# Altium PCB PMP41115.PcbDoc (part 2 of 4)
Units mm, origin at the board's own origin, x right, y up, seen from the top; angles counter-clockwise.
Board outline 97.92 x 43.13 mm, 4 copper layers (Top Layer, Signal Layer 1, Signal Layer 2, Bottom Layer), stack 1.016 mm thick; 168 components, 122 nets, 522 pads, 2459 vias.
Unrouted connection lines stored in the file: 1.
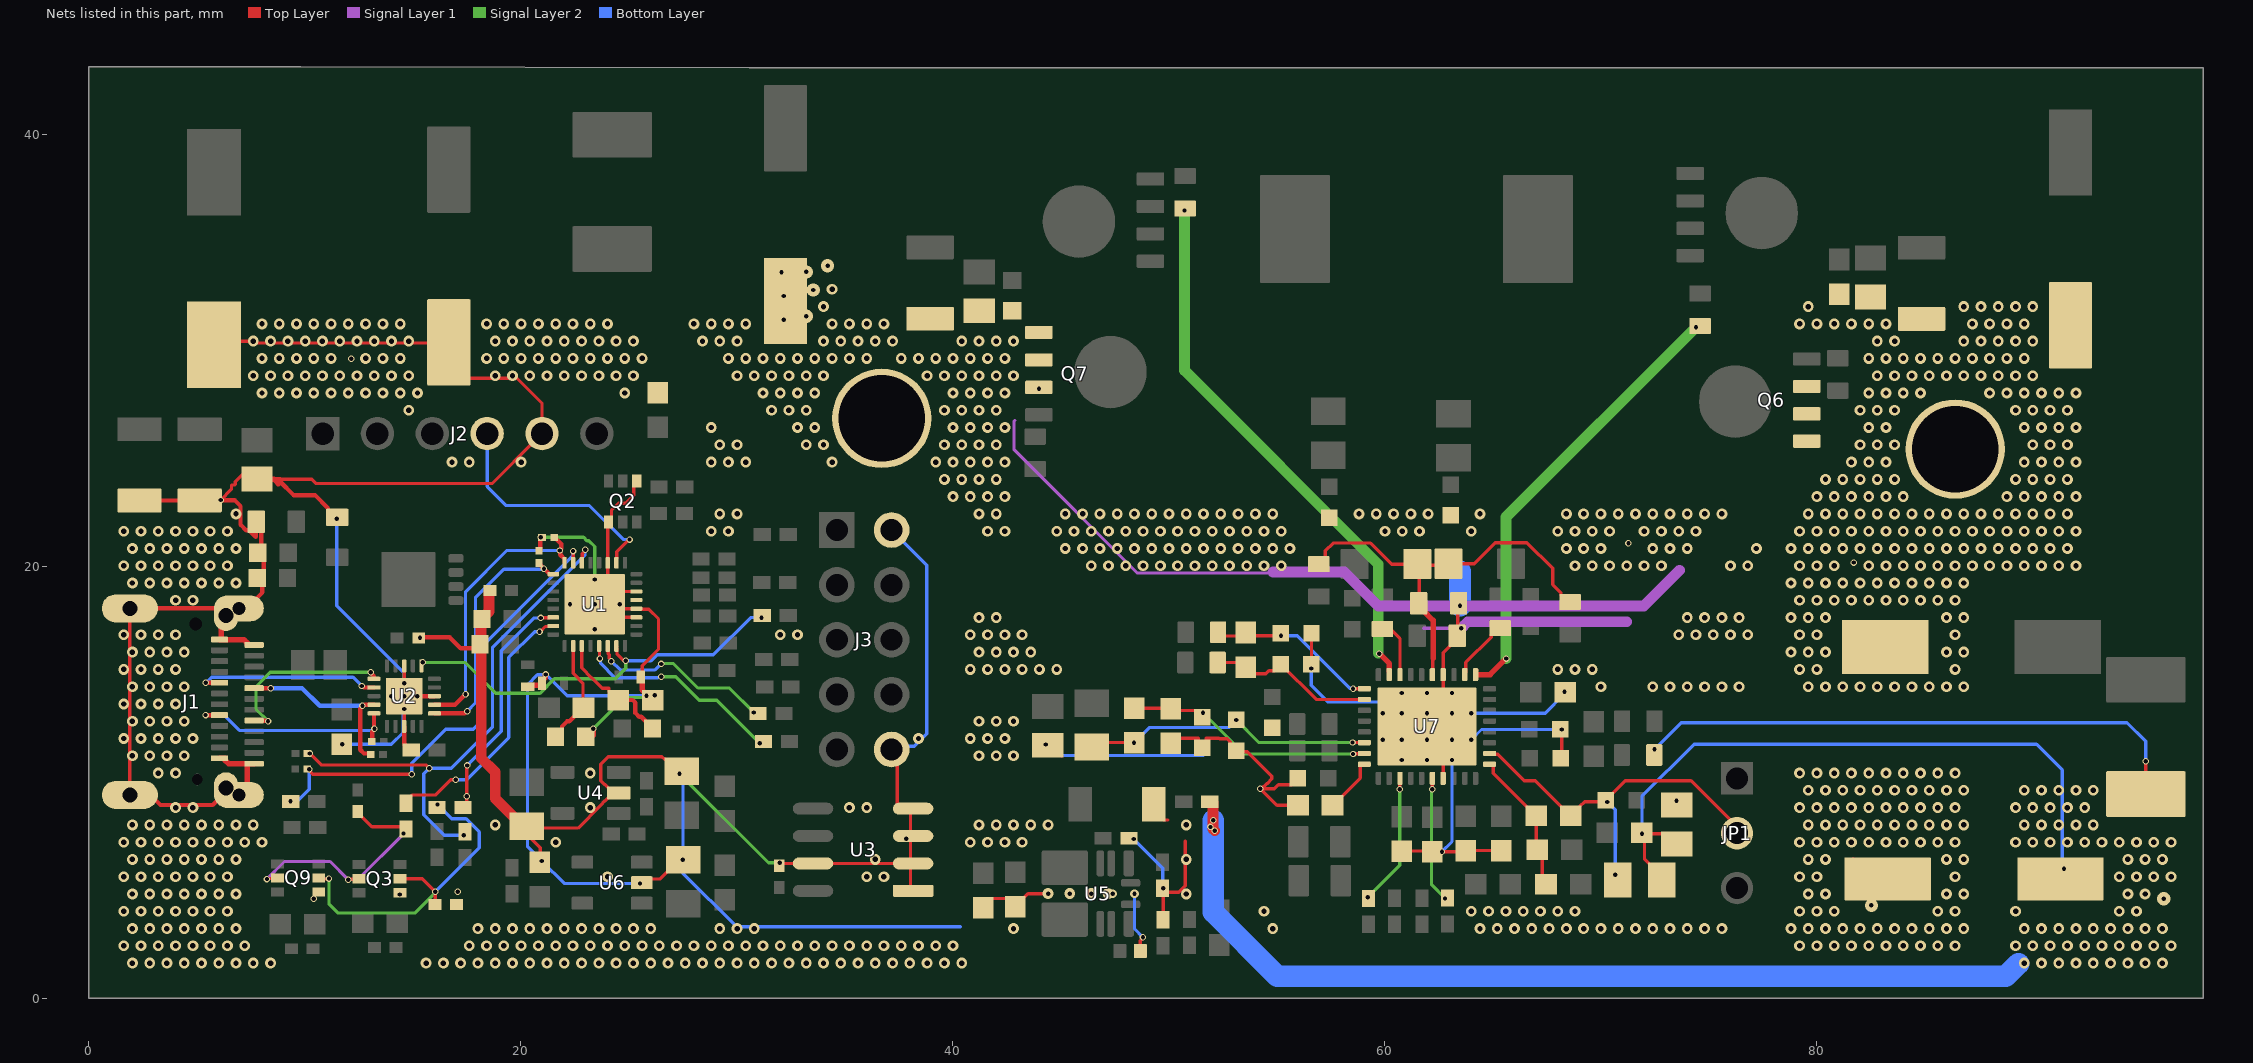
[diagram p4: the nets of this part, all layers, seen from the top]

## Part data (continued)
R31 R32 R35 R36: library part CMP-0093685-1, "RES Thick Film, 10Ω, 1%, 0.1W, 100ppm/°C, 0603", Approved Alternate Part Number=541-1.00HHCT-ND, Manufacturer=Vishay, Operating Temperature Range="-55°C to +155°C", Power=100mW, TempCo=100ppm/°C, Tolerance_%=1%, Voltage=75V
R34 R37 R43 R44 R49 R50 R53 R54 R55 R56: library part CMP-0093629-1, "Thick Film Resistors - SMD 1/10watt ZEROohm Jumper", Manufacturer=Vishay, Operating Temperature Range="-55°C to +155°C", Power=250mW, Power_W=330mW, TempCo=100ppm/°C, Tolerance_%=1%
R38: library part CMP-0023199-5, "RES, 5.23 k, 1%, 0.1 W, 0603", Manufacturer=Yageo, Power_W=100mW, Supplier Part Number 1=311-5.23KHRCT-ND, TempCo="100 ppm/C", Tolerance_%=1%, Value2=0.1W, Value_Code=5k23, ValueDisplayed=5.23k
R39: library part CMP-0022684-2, "RES, 10.0 k, 1%, 0.1 W, 0603", Manufacturer=Panasonic, Power_W=100mW, Supplier Part Number 1=P10.0KHCT-ND, TempCo="100 ppm/C", Tolerance_%=1%, Value2=0.1W, Value_Code=10k0, ValueDisplayed=10.0k
R40: library part CMP-0023018-5, "RES, 30.1 k, 1%, 0.1 W, 0603", Manufacturer=Yageo, Power_W=100mW, Supplier Part Number 1=311-30.1KHRCT-ND, TempCo="100 ppm/C", Tolerance_%=1%, Value2=0.1W, Value_Code=30k1, ValueDisplayed=30.1k
R41 R42: library part CMP-0020812-2, "RES, 2.2, 5%, 0.125 W, 0805", Manufacturer="Yageo America", Power_W=125mW, Supplier Part Number 1=311-2.2ARCT-ND, TempCo="200 ppm/C", Tolerance_%=5%, Value2=0.125W, Value_Code=2R20, ValueDisplayed=2.2
R45: library part CMP-0021522-3, "Thick Film Resistors - SMD 1/8Watt 1Mohms 1% Commercial Use", Manufacturer="Vishay / Dale", Power_W=125mW, Supplier Part Number 1=P1.00MCCT-ND, TempCo="100 ppm/C", Tolerance_%=1%, Value2=0.125W, Value_Code=1M00, ValueDisplayed=1.00M
R46: library part CMP-0024170-1, "RES, 383 k, 0.1%, 0.1 W, 0603", Manufacturer="Yageo America", Power_W=100mW, TempCo="25 ppm/C", Tolerance_%=0.1%, Value2=0.1W, Value_Code=383k
R47: library part CMP-0024106-3, "RES, 31.2 k, 0.1%, 0.1 W, 0603", Manufacturer="Yageo America", Power_W=100mW, TempCo="25 ppm/C", Tolerance_%=0.1%, Value2=0.1W, Value_Code=31k2, ValueDisplayed=31.2k
R51: library part CMP-0025744-3, "RES, 1.1, 5%, 0.1 W, 0603", Manufacturer=Vishay-Dale, Power_W=100mW, Supplier Part Number 1=541-1.1GCT-ND, TempCo="200 ppm/C", Tolerance_%=5%, Value2=0.1W, Value_Code=1R10, ValueDisplayed=1.1
R52: library part CMP-0018933-2, "Thick Film Resistors - SMD 0805 Anti-Surge Res. 0.1%, 249Kohm", Manufacturer=Panasonic, Power_W=125mW, Supplier Part Number 1=RG20P249KBCT-ND, TempCo="25 ppm/C", Tolerance_%=0.1%, Value2=0.125W, Value_Code=249k
R57: library part CMP-0023733-2, "RES, 13.7 k, 0.1%, 0.1 W, 0603", Manufacturer="Yageo America", Power_W=100mW, TempCo="25 ppm/C", Tolerance_%=0.1%, Value2=0.1W, Value_Code=13k7, ValueDisplayed=13.7k
R58: library part CMP-0024097-2, "RES, 30.5 k, 0.1%, 0.1 W, 0603", Manufacturer="Yageo America", Power_W=100mW, TempCo="25 ppm/C", Tolerance_%=0.1%, Value2=0.1W, Value_Code=30k5, ValueDisplayed=30.5k
R59: library part CMP-0023735-1, "RES, 13.0 k, 0.1%, 0.1 W, 0603", Manufacturer="Yageo America", Power_W=100mW, TempCo="25 ppm/C", Tolerance_%=0.1%, Value2=0.1W, Value_Code=13k0, ValueDisplayed=13.0k
R61: library part CMP-0022371-2, "RES, 3.01 k, 1%, 0.1 W, 0603", Manufacturer=Vishay-Dale, Power_W=100mW, Supplier Part Number 1=541-3.01KHCT-ND, TempCo="100 ppm/C", Tolerance_%=1%, Value2=0.1W, Value_Code=3k01, ValueDisplayed=3.01k
R63 R64: library part CMP-0092857-1, "Thick Film Resistors - SMD 1/8watt ZEROohm Jumper", Manufacturer=Vishay, Operating Temperature Range="-55°C to +155°C", Power_W=500mW, TempCo=200ppm/°C, Tolerance_%=5%
R65: library part CMP-0023086-5, "RES, 3.60 k, 1%, 0.1 W, 0603", Manufacturer=Yageo, Power_W=100mW, Supplier Part Number 1=311-3.60KHRCT-ND, TempCo="100 ppm/C", Tolerance_%=1%, Value2=0.1W, Value_Code=3k60, ValueDisplayed=3.60k
R67 R68 R69 R70: library part CMP-0078781-1, "RES, 10.5 k, 1%, 0.063 W, 0402", Manufacturer="Yageo America", Power_W=63mW, Supplier Part Number 1=YAG2951CT-ND, TempCo="100 ppm/C", Tolerance_%=1%, Value2=0.063W, Value_Code=10k5, ValueDisplayed=10.5k
R71: library part CMP-0023607-3, "RES, 8.20 k, 0.1%, 0.1 W, 0603", Manufacturer="Susumu Co Ltd", Power_W=100mW, Supplier Part Number 1=RG16P8.2KBCT-ND, TempCo="25 ppm/C", Tolerance_%=0.1%, Value2=0.1W, Value_Code=8k20, ValueDisplayed=8.20k
R97 R108: library part CMP-0026745-1, "RES, 100 k, 1%, 0.063 W, 0402", Manufacturer="Samsung Electro-Mechanics", Power_W=63mW, Supplier Part Number 1=1276-3432-1-ND, TempCo="100 ppm/C", Tolerance_%=1%, Value2=0.063W, Value_Code=100k
R101 R102: library part CMP-0023490-1, "RES, 249 k, 0.1%, 0.1 W, 0603", Manufacturer="Susumu Co Ltd", Power_W=100mW, Supplier Part Number 1=RG16P249KBCT-ND, TempCo="25 ppm/C", Tolerance_%=0.1%, Value2=0.1W, Value_Code=249k
R105 R106: library part CMP-0026660-1, "RES, 1.00 M, 1%, 0.1 W, 0402", Manufacturer=Panasonic, Power_W=100mW, Supplier Part Number 1=P1.00MLCT-ND, TempCo="100 ppm/C", Tolerance_%=1%, Value2=0.1W, Value_Code=1M00, ValueDisplayed=1.00M
U1: library part CMP-0121143-2, "USB Type-C® and USB PD Controller with Integrated Power Switches Optimized for Power Applications", Manufacturer="Texas Instruments", Max Supply Voltage=22V, Min Supply Voltage=3V, Nominal Supply Current=1-3mA, Operating Temperature Range="-40°C to +125°C"
U2: library part CMP-0034161-1, "USB Type-C® 48V EPR Port Protector: Short-to-VBUS Overvoltage and IEC ESD Protection", Manufacturer="Texas Instruments", Operating Supply Voltage=3.3V, Operating Temperature Range="-40°C to +125°C"
U3: library part CMP-0091847-1, "EEPROM Memory IC 512Kb (64K x 8) I²C 1MHz 900ns 8-SOIC", Digikey Part Number=CAT24C512WI-GT3OSCT-ND, Frequency_Fixed=1MHz, Manufacturer="ON Semi", Max Supply Voltage=5.5V, Min Supply Voltage=1.8V, Mouser Part Number=863-CAT24C512WI-GT3, Operating Temperature Range="-40°C to +85°C"
U4: library part CMP-0096923-1, "Linear Voltage Regulator IC  1 Output  200mA SOT-23-5", Digikey Part Number=296-TPS7A2450DBVRCT-ND, Dropout Voltage=160mV, Manufacturer="Texas Instruments", Max Supply Voltage=18V, Min Supply Voltage=2.4V, Mouser Part Number=595-TPS7A2450DBVR, Nominal Supply Current=2-15uA, Operating Temperature Range="-40°C to +125°C", Output Voltage=5V
U5: library part CMP-0096774-1, "3 V to 65 V Input, 1 V to 13 V Output, 600-mA Synchronous Buck Converter Power Module in a HotRod™ QFN Package", Manufacturer="Texas Instruments", Max Supply Voltage=65V, Min Supply Voltage=3.6V, Nominal Supply Current=17-18uA, Operating Temperature Range="-40°C to +125°C", Output Voltage=1-13V, Switching Frequency=200-2200kHz
U6: library part CMP-0035539-1, "Single Output LDO, 150 mA, Fixed 3.3 V Output, 2.7 to 10 V Input, with Low IQ, 5-pin SOT-23 (DBV), -40 to 125 degC, Green (RoHS & no Sb/Br)", Manufacturer="Texas Instruments"
U7: library part CMP-0093460-1, Alternate Manufacturer=None, Manufacturer="Texas Instruments", Operating Temperature Range=to

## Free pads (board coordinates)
  round 4.6 hole 4: 2(36.723,26.845) 2(86.431,25.423)

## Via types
v1: diameter 0.5, hole 0.25, Top Layer to Bottom Layer, 2147 vias
v2: diameter 0.3, hole 0.2, Top Layer to Bottom Layer, tented both sides, 193 vias
v3: diameter 0.5, hole 0.25, Top Layer to Bottom Layer, tented both sides, 61 vias
v4: diameter 0.5, hole 0.2, Top Layer to Bottom Layer, 22 vias
v5: diameter 0.5, hole 0.2, Top Layer to Bottom Layer, tented both sides, 19 vias
v6: diameter 0.61, hole 0.203, Top Layer to Bottom Layer, tented both sides, 13 vias
v7: diameter 0.35, hole 0.2, Top Layer to Bottom Layer, tented both sides, 2 vias
v8: diameter 0.4, hole 0.2, Top Layer to Bottom Layer, tented both sides, 2 vias

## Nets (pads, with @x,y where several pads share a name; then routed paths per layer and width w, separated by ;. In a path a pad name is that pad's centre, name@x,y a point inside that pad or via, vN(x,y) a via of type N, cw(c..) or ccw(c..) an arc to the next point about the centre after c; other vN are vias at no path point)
/INT: R68.1 U7.3 | length 6.1
  Top Layer w0.152: v2@60.706,9.703 60.712,9.709 60.712,10.172 U7.3@60.718,10.178
  Signal Layer 2 w0.152: v2(59.222,4.665) 60.706,6.149 v2(60.706,9.677)
/PG: R67.1 U7.6 | length 5.7
  Top Layer w0.152: U7.6@62.218,10.178 62.216,10.176 62.216,9.691 v2@62.23,9.677
  Signal Layer 2 w0.152: v2@62.179,9.576 62.179,5.239 v2(62.804,4.615)
  other v2: 62.214,9.677
ACN: C29.2 C33.1 R32.1 U7.29 | length 8.4
  Top Layer w0.152: R32.1@52.298,16.944 52.478,16.764 53.416,16.764 C29.2@53.581,16.929 ; v2(55.209,16.781) 55.2,16.781 C29.2@53.729,16.781 ; v2(58.547,14.326) v2(58.547,14.326) 59.067,14.327 U7.29@59.068,14.328 ; C29.2@53.581,16.929 C29.2@53.729,16.781 ; C29.2@53.581,16.929 C29.2@53.729,16.781 ; C29.2@53.581,16.929 C29.2@53.729,16.781
  Bottom Layer w0.152: v2(55.209,16.781) 55.964,16.781 58.392,14.354 58.519,14.354 v2(58.547,14.326)
ACOV: C39.1 R46.1 R47.2 U7.35 | length 11.7
  Top Layer w0.152: R46.1@48.421,13.42 50.112,13.42 R47.2@50.112,13.395 ; R47.2@50.165,13.437 50.281,13.32 51.435,13.32 51.571,13.184 C39.1@51.571,13.016 ; v2(58.547,11.303) 58.559,11.315 58.89,11.315 U7.35@58.903,11.303
  Top Layer w0.254: C39.1@51.571,13.016 51.571,13.193 v2(51.598,13.221)
  Signal Layer 2 w0.152: v2(51.598,13.221) 53.516,11.303 v2(58.547,11.303)
ACP: C29.1 C32.1 R31.1 U7.30 | length 7.9
  Top Layer w0.152: R31.1@52.277,15.539 53.472,15.539 53.632,15.38 53.632,15.253 53.861,15.024 54.512,15.024 54.65,15.162 54.893,15.162 C32.1@55.198,15.467 56.837,13.828 U7.30@59.068,13.828
ACUV: C38.1 R45.1 R46.2 U7.34 | length 13.3
  Top Layer w0.152: R45.1@46.452,11.629 46.659,11.836 R46.2@48.336,11.836 ; v2(58.522,11.836) 58.526,11.832 58.848,11.832 U7.34@58.877,11.862
  Signal Layer 2 w0.152: v2(53.138,12.88) 54.181,11.836 v2(58.522,11.836)
  Bottom Layer w0.152: v2(48.402,11.828) 49.103,12.529 52.788,12.529 v2(53.138,12.88)
ADCIN1: R13.1 R15.2 U1.2 | length 5
  Top Layer w0.152: U1.2@22.435,16.307 22.435,15.041 22.478,14.998 22.478,14.987 22.888,14.577 R13.1@22.888,13.448
  Top Layer w0.2: R15.2@21.616,12.099 21.916,12.399 21.916,12.578 22.151,12.813 22.253,12.813 22.888,13.448 R13.1@22.913,13.448
ADCIN2: R14.1 R16.2 U1.3 | length 5.8
  Top Layer w0.152: U1.3@22.835,16.307 22.835,15.29 23.304,14.821 23.312,14.821 23.782,14.352 24.089,14.352 24.089,14.276 ; R16.2@24.089,14.275 24.089,14.199 24.488,13.801 R16.2@24.513,13.801
  Top Layer w0.2: R16.2@24.513,13.801 25.196,13.801 25.313,13.683 25.313,13.201 25.489,13.026 25.588,13.026 26.105,12.508 R14.1@26.105,12.483
BAT: C60.2 C64.1 R23.2 R33.2 R36.1 R51.2 R52.2 | length 103.7
  Top Layer w0.152: R23.2@51.907,9.092 51.943,9.056 v2(51.943,7.925) ; R52.2@72.832,5.469 72.832,5.634 72.045,6.421 72.045,7.489 v2(71.922,7.612) 73.058,7.612 C64.1@73.532,7.138 ; v2(95.25,10.973) 95.25,10.236 R33.2@95.326,10.16
  Top Layer w0.254: C60.2@91.302,5.519 91.465,5.682 v6(91.465,5.994)
  Top Layer w0.5: R23.2@51.907,9.092 52.007,9.092 52.057,9.042 52.057,7.836 v2(52.146,7.747)
  Bottom Layer w0.152: v2(71.922,7.612) 71.922,9.337 74.346,11.76 90.195,11.76 91.389,10.566 91.389,5.918 v6@91.567,5.74 ; v2@72.517,11.523 72.517,11.534 73.737,12.754 94.383,12.754 95.25,11.887 v2(95.25,10.973)
  Bottom Layer w0.5: v2(51.943,7.925) v2@52.07,7.798 ; v2@52.133,7.734 52.133,7.747 v2(52.146,7.747)
  Bottom Layer w1: v2(52.07,8.23) 52.07,7.798 52.07,3.988 55.042,1.016 88.773,1.016 89.357,1.6
  other v1: 89.623,1.621 90.423,1.621 91.223,1.621 92.023,1.621 92.823,1.621 93.623,1.621 94.423,1.621 95.223,1.621 96.023,1.621 89.223,2.421 90.023,2.421 90.823,2.421 91.623,2.421 92.423,2.421 93.223,2.421 94.023,2.421 94.823,2.421 95.623,2.421 96.423,2.421 89.623,3.221 90.423,3.221 91.223,3.221 92.023,3.221 92.823,3.221 93.623,3.221 94.423,3.221 95.223,3.221 96.023,3.221 89.223,4.021 94.023,4.021 94.823,4.021 94.423,4.821 95.223,4.821 94.023,5.621 94.823,5.621 95.623,5.621 96.423,5.621 94.423,6.421 95.223,6.421 96.023,6.421 89.223,7.221 90.023,7.221 90.823,7.221 91.623,7.221 92.423,7.221 93.223,7.221 94.023,7.221 94.823,7.221 95.623,7.221 96.423,7.221 89.623,8.021 90.423,8.021 91.223,8.021 92.023,8.021 92.823,8.021 89.223,8.821 90.023,8.821 90.823,8.821 91.623,8.821 92.423,8.821 89.623,9.621 90.423,9.621 91.223,9.621 92.023,9.621 92.823,9.621
  other v2: 72.507,11.523
  other v6: 96.088,4.597
BTST1: R49.1 U7.26 | length 2.7
  Top Layer w0.152: R49.1@59.903,17.09 59.976,17.018 60.355,17.018 60.718,16.654 U7.26@60.718,14.978
BTST2: R50.1 U7.20 | length 2.8
  Top Layer w0.152: U7.20@63.754,15.062 63.767,15.075 63.767,15.545 64.938,16.716 64.938,16.836 65.237,17.135 R50.1@65.362,17.135
C_CC1: J1.A5 R10.2 U2.4 | length 8.6
  Top Layer w0.2: J1.A5@7.658,14.353 8.481,14.353 v2@8.484,14.351 ; v2(12.675,13.534) 12.675,13.507 12.572,13.404 12.572,11.501 12.748,11.325 13.009,11.325 R10.2@13.064,11.271 ; v2@12.715,13.524 12.775,13.584 U2.4@13.21,13.584
  Bottom Layer w0.2: v2@8.452,14.332 v2(8.433,14.351) 9.881,14.351 10.698,13.534 12.628,13.534 v2@12.649,13.513
C_CC2: J1.B5 R11.2 U2.5 | length 10.1
  Top Layer w0.2: v2(5.41,13.106) 5.412,13.105 6.056,13.105 J1.B5@6.058,13.103 ; R11.2@13.103,11.887 13.136,11.92 13.136,12.347 13.214,12.425 13.214,12.467 13.21,12.471 U2.5@13.21,13.184
  Bottom Layer w0.152: v2(5.41,13.106) 6.268,13.106 6.98,12.395 13.117,12.395 13.193,12.471 v2(13.233,12.471)
C_SBU1: J1.A8 U2.1 | length 8.4
  Top Layer w0.2: J1.A8@7.658,12.853 7.671,12.84 8.293,12.84 v2(8.306,12.827) ; v2(13.056,15.088) 13.056,15.061 13.208,14.908 U2.1@13.208,14.808
  Signal Layer 2 w0.152: v2(8.306,12.827) 7.747,13.386 7.747,14.427 8.407,15.088 13.005,15.088 v2@13.056,15.138
C_SBU2: J1.B8 U2.2 | length 8.7
  Top Layer w0.2: v2@5.385,14.63 5.412,14.603 v2(5.418,14.603) J1.B8@6.058,14.603 ; v2(12.649,14.453) 12.676,14.453 12.745,14.384 U2.2@13.21,14.384
  Bottom Layer w0.152: v2(5.418,14.603) 5.442,14.603 5.698,14.859 12.243,14.859 12.601,14.501 12.601,14.481 v2@12.598,14.478
CC1: C9.1 U1.24 U2.12 | length 13
  Top Layer w0.2: U2.12@16.01,13.584 16.96,13.584 17.448,14.072 v2(17.45,14.072) ; C9.1@21.553,21.337 21.573,21.337 21.886,21.025 21.886,20.821 21.819,20.753 v2(21.819,20.726) 21.838,20.707 21.838,20.529 22.035,20.332 U1.24@22.035,20.157
  Bottom Layer w0.152: v2(17.45,14.072) 17.45,18.821 19.355,20.726 v2(21.819,20.726)
CC2: C8.1 U1.25 U2.11 | length 11.5
  Top Layer w0.2: U2.11@16.01,13.184 17.398,13.184 17.499,13.284 v2(17.526,13.284) ; C8.1@20.879,20.117 20.914,20.082 20.914,20.053 21.335,19.632 U1.25@21.51,19.632
  Bottom Layer w0.152: v2(17.526,13.284) 17.907,13.665 17.907,18.542 19.228,19.863 21.014,19.863 21.031,19.88 v2@21.031,19.888
  other v2: 21.082,19.888
DRV_SUP: C43.1 D3.2 D4.2 R53.2 R55.2 U7.23 | length 20.2
  Top Layer w0.152: R53.2@56.961,20.096 56.964,20.096 57.263,20.395 57.263,20.712 57.623,21.072 59.356,21.072 60.333,20.096 D3.2@61.522,20.096 61.522,19.656 D3.2@61.633,19.546 ; C43.1@61.583,18.288 61.608,18.313 61.608,19.52 D3.2@61.633,19.546 ; D3.2@61.595,20.041 62.889,20.041 D4.2@62.962,20.114 64.152,20.114 65.128,21.09 66.596,21.09 67.788,19.898 67.788,19.148 68.171,18.764 68.171,18.639 68.47,18.341 R55.2@68.595,18.341 ; D3.2@61.633,19.985 D3.2@61.633,19.546 ; U7.23@62.218,14.978 62.237,14.996 62.237,15.704 62.255,15.723
  Top Layer w0.254: C43.1@61.773,17.973 62.255,17.49 62.255,15.735
"E_Fuse Source": J2.4 U1.18 | length 11.2
  Top Layer w0.152: U1.18@24.438,20.345 24.448,20.355 24.448,20.678 25.004,21.234 v2(25.044,21.234)
  Bottom Layer w0.152: J2.4@18.451,26.141 18.451,23.688 19.329,22.809 23.19,22.809 24.765,21.234 v2(25.044,21.234)
EPR_EN: R48.1 U1.7 U2.16 | length 18.7
  Top Layer w0.152: U1.7@24.435,16.205 U1.7@24.459,16.181 ; U1.7@24.435,16.307 U1.7@24.459,16.283 ; U1.7@24.459,16.129 24.459,15.946 24.756,15.649 24.838,15.649 v2(24.867,15.621)
  Signal Layer 2 w0.152: v2(15.469,15.545) 17.424,15.545 18.85,14.119 20.901,14.119 21.565,14.783 24.384,14.783 24.867,15.265 v2(24.867,15.621)
  Bottom Layer w0.152: v2(24.867,15.621) 26.042,15.621 26.321,15.9 28.931,15.9 30.65,17.619 v2(31.155,17.619)
FB: C42.2 JP1.2 R52.1 R57.2 U7.12 | length 18.1
  Top Layer w0.152: U7.12@64.868,11.328 64.908,11.288 65.242,11.288 66.466,10.064 66.987,10.064 68.601,8.45 68.651,8.45 69.049,8.849 69.049,8.874 69.269,9.093 C42.2@70.255,9.093 ; v2(70.322,9.085) 70.322,9.237 71.144,10.058 74.197,10.058 76.325,7.931 JP1.2@76.325,7.635
  Bottom Layer w0.152: v2(70.322,9.085) 70.688,8.719 v2(70.688,5.715)
FBG: R57.1 R58.1 R59.1 U7.11 | length 6.6
  Top Layer w0.152: U7.11@64.868,10.828 64.993,10.828 65.042,10.779 65.042,10.409 66.802,8.649 R57.1@66.802,8.382 ; R58.1@67.026,6.904 R57.1@67.026,8.45 ; R58.1@67.079,6.873 67.31,6.642 67.31,5.443 R59.1@67.482,5.272
FSW_SYNC: R62.2 U7.36 | length 2.6
  Top Layer w0.152: R62.2@57.596,8.925 57.621,8.925 58.884,10.187 58.884,10.779 58.9,10.795 U7.36@59.08,10.795
GND: C1.2 C2.2 C3.1 C4.2 C5.2 C6.1 C8.2 C9.2 C10.2 C11.1 C12.2 C13.2 C14.2 C15.2 C16.1 C17.1 C18.2 C19.2 C20.2 C21.2 C22.2 C23.2 C25.2 C26.2 C27.2 C28.2 C31.1 C32.2 C33.2 C34.2 C35.2 C36.2 C37.2 C38.2 C39.2 C43.2 C44.1 C45.2 C46.2 C47.1 C48.1 C49.2 C50.2 C51.1 C52.1 C53.2 C54.2 C55.1 C56.2 C57.2 C59.2 C60.1 C62.2 C64.2 C80.1 J1.A1 J1.A12 J1.B1 J1.B12 J1.S1 J1.S2 J1.S3 J1.S4 J2.5 J3.2 J3.10 pad.2 Q2.1 Q2.4 Q3.4 Q6.1 Q6.2 Q6.3 Q7.1 Q7.2 Q7.3 Q9.4 R15.1 R16.1 R28.1 R29.1 R39.1 R40.1 R47.1 R61.1 R62.1 R65.1 R71.1 R108.1 U1.11 U1.12 U1.14 U1.19 U1.33 U2.8 U2.13 U2.18 U2.21 U3.1 U3.2 U3.3 U3.4 U3.7 U4.2 U5.10 U6.2 U7.7 U7.22 U7.37 | length 333.1
  Top Layer w0.152: J1.S3@1.908,18.048 1.908,16.021 1.908,14.421 1.908,12.821 1.908,11.221 J1.S4@1.908,9.408 1.908,9.395 J1.S4@1.93,9.373 ; C57.2@5.796,30.248 5.969,30.421 7.542,30.421 7.623,30.339 8.423,30.339 9.223,30.339 10.023,30.339 10.823,30.339 11.623,30.339 12.423,30.339 13.223,30.339 14.023,30.339 v1@14.823,30.339 ; v2(6.121,23.063) 6.612,23.553 6.612,23.76 6.764,23.76 6.787,23.783 6.787,23.91 7.111,24.234 7.136,24.234 7.2,24.17 7.342,24.028 C59.2@7.418,24.028 ; C59.2@7.238,24.209 C59.2@7.418,24.028 ; C59.2@7.79,24.031 7.422,24.031 C59.2@7.418,24.028 ; 8.871,24.031 10.323,24.031 10.53,23.825 18.675,23.825 20.656,25.806 21.006,25.806 20.991,25.822 20.991,27.544 19.833,28.702 19.623,28.702 v1@18.823,28.702 ; U2.21@14.58,14.732 14.585,14.732 14.61,14.757 U2.18@14.61,15.384 ; U2.8@14.61,12.584 14.61,13.289 U2.21@14.63,13.31 ; v1(14.823,30.421) v1@14.823,30.339 ; C20.2@20.278,7.958 20.361,7.874 C20.2@20.371,7.874 ; C27.2@20.904,6.401 20.904,6.96 20.371,7.493 C20.2@20.371,7.874 ; U1.33@24.054,19.507 24.035,19.526 U1.19@24.035,20.157 24.035,21.901 Q2.1@24.105,21.971 ; Q2.1@24.079,22.052 24.206,22.179 24.206,22.58 24.536,22.911 24.867,22.911 25.245,23.289 25.245,23.728 25.291,23.774 Q2.4@25.324,23.774 ; U4.2@24.486,9.5 24.286,9.5 23.916,9.129 23.905,9.129 23.713,8.937 23.713,8.927 22.661,7.874 C20.2@20.371,7.874 ; U4.2@24.54,9.503 24.29,9.503 23.916,9.877 23.905,9.877 23.713,10.068 23.713,10.837 24.052,11.176 26.543,11.176 26.665,11.054 26.737,11.054 27.076,10.715 C19.2@27.076,10.643 ; U1.33@24.587,18.847 24.602,18.832 U1.14@25.36,18.832 ; U1.33@24.689,17.653 24.71,17.632 U1.11@25.36,17.632 ; U1.33@24.689,18.034 24.691,18.032 U1.12@25.36,18.032 25.384,18.008 25.934,18.008 26.385,17.557 26.385,16.149 25.633,15.397 25.633,14.939 C17.1@25.558,14.864 ; U6.2@25.612,5.344 25.784,5.516 26.475,5.516 27.127,6.168 C28.2@27.127,6.299 ; C12.2@31.852,6.198 31.89,6.236 U3.7@33.541,6.236 37.783,6.236 U3.2@37.795,6.248 ; J3.10@37.182,11.514 37.434,11.262 37.434,8.957 37.475,8.915 U3.4@37.846,8.915 ; U3.1@38.049,5.182 38.049,8.652 U3.4@38.173,8.776 ; C25.2@41.423,4.19 41.423,4.215 41.822,4.613 42.519,4.613 C26.2@42.906,4.227 ; C26.2@42.906,4.252 43.492,4.839 v5(44.425,4.839) ; v2(44.315,11.745) 44.516,11.745 C45.2@45.054,11.207 ; v8(48.425,4.839) v8@48.469,4.795 ; C23.2@48.698,2.184 48.698,2.662 48.819,2.782 v2(48.819,2.819) v2@48.819,2.845 ; C21.2@49.319,8.968 49.319,8.718 49.793,8.244 49.973,8.244 ; R29.1@49.752,3.623 49.752,4.896 R28.1@49.759,4.902 ; R28.1@49.835,4.978 R28.1@49.759,4.902 ; R47.1@50.013,11.938 50.11,12.035 51.391,12.035 51.391,11.773 C39.2@51.571,11.593 51.751,11.774 51.751,12.035 52.337,12.035 52.36,12.012 52.718,12.012 52.859,11.872 52.859,11.736 C38.2@53.138,11.457 53.193,11.403 53.656,11.403 54.785,10.274 54.785,10.148 54.572,9.935 54.539,9.935 54.324,9.719 54.324,9.691 54.906,9.691 55.091,9.877 55.702,9.877 C44.1@55.982,10.156 ; 50.775,7.263 50.775,5.207 50.47,4.902 R28.1@49.759,4.902 ; v2(54.256,9.691) 55.022,8.925 R62.1@55.996,8.925 ; C32.2@56.621,15.468 C33.2@56.623,16.902 C33.2@56.623,16.902 ; R40.1@60.8,6.807 62.193,6.807 R39.1@62.223,6.777 62.253,6.807 62.636,6.807 v2(62.662,6.782) 63.678,6.782 R71.1@63.754,6.858 ; U7.37@61.968,12.578 62.713,13.322 62.713,14.199 62.718,14.204 U7.22@62.718,14.978 62.718,16.002 63.271,16.555 C46.2@63.271,16.612 ; U7.37@62.713,10.947 62.718,10.942 U7.7@62.718,10.178 ; C43.2@63.433,18.288 C43.2@63.433,18.22 ; v2(63.5,18.161) 63.441,18.22 C43.2@63.433,18.22 ; v2(63.551,17.12) 63.54,17.12 63.5,17.16 63.465,17.16 63.4,17.225 63.4,18.128 63.433,18.161 C43.2@63.433,18.22 ; R71.1@64.059,6.833 65.394,6.833 R65.1@65.399,6.827 ; C34.2@68.137,12.454 C34.2@68.163,12.454 ; C35.2@68.157,11.106 68.214,11.163 68.214,12.454 C34.2@68.163,12.454 ; C34.2@68.378,12.668 C34.2@68.163,12.454 ; v1@14.823,30.339 16.65,30.339 C55.1@16.675,30.365 16.371,30.06 16.371,29.949 17.498,28.822 17.498,28.702 v1@18.823,28.702 ; v1@18.823,28.702 v1(18.823,28.821) ; v1@18.823,28.702 v1(18.823,28.821) ; v1@18.823,28.702 v1(18.823,28.821)
  Top Layer w0.2: J1.S3@1.908,18.048 1.922,18.034 2.87,18.034 2.885,18.048 6.358,18.048 J1.S1@6.958,18.048 ; C31.1@2.349,23.039 2.654,23.039 2.658,23.042 5.135,23.042 C56.2@5.138,23.046 ; J1.S4@2.616,9.22 3.044,9.22 3.323,8.941 4.023,8.941 4.823,8.941 5.74,8.941 6.358,9.558 J1.S2@6.358,9.733 ; v2(6.121,23.063) 6.139,23.046 6.768,23.046 7.033,22.781 7.033,21.924 7.298,21.659 7.436,21.659 7.729,21.365 7.729,21.434 7.742,21.446 7.742,22.038 C3.1@7.762,22.059 7.992,21.829 7.992,20.782 C5.2@7.834,20.625 8.109,20.35 8.109,19.756 C4.2@7.809,19.456 8.042,19.223 8.042,18.786 7.304,18.048 J1.S1@6.958,18.048 ; J1.S1@7.251,17.755 J1.S1@6.958,18.048 ; 8.577,24.031 8.871,24.031 8.871,23.91 9.489,23.292 10.475,23.292 11.081,22.686 11.081,22.561 11.381,22.261 C80.1@11.506,22.261 11.506,22.225 v2(11.481,22.2) ; U2.8@14.61,12.584 14.61,11.801 14.633,11.777 14.633,11.683 14.833,11.483 C10.2@14.933,11.483 ; C1.2@15.283,16.678 15.309,16.703 16.719,16.703 17.227,16.195 17.932,16.195 C13.2@18.116,16.379 ; U2.21@15.316,13.995 15.328,13.984 U2.13@16.01,13.984 ; C15.2@18.587,18.877 C15.2@18.618,18.846 ; C8.2@20.854,20.711 20.914,20.771 20.914,21.277 20.974,21.337 C9.2@20.993,21.337 ; v2(25.832,13.995) 26.187,13.995 v2(26.213,14.021)
  Top Layer w0.254: J1.B1@6.058,11.103 6.323,11.103 6.331,11.095 6.331,11.002 6.48,10.853 J1.A12@7.343,10.853 ; J1.S1@6.358,17.723 6.358,17.319 6.136,17.098 6.136,16.611 6.128,16.603 J1.B12@6.058,16.603 6.066,16.595 7.186,16.595 7.335,16.447 7.335,16.361 7.343,16.353 J1.A1@7.658,16.353 ; J1.S2@6.958,9.408 7.343,9.793 J1.A12@7.343,10.853 ; J1.A12@7.658,10.853 J1.A12@7.343,10.853 ; C59.2@7.79,24.031 8.577,24.031 8.784,23.825 ; C18.2@20.333,14.418 20.397,14.482 20.932,14.482 20.995,14.545 C16.1@20.995,14.578 20.995,14.693 21.149,14.847 21.149,14.977 v2(21.158,14.986) ; R15.1@23.156,11.96 23.369,12.173 v2(23.369,12.475) ; C17.1@25.558,14.864 25.622,14.8 25.622,14.267 25.85,14.039 25.875,14.039 25.893,14.021 v2(26.213,14.021) ; C48.1@32.268,32.279 32.78,32.791 33.223,32.791 v6(33.553,32.791) ; C60.1@81.712,6.392 82.585,5.519 C60.1@83.302,5.519
  Top Layer w0.5: C15.2@18.567,18.877 18.537,18.877 18.537,17.904 18.211,17.579 C14.2@18.211,17.554 18.164,17.506 18.164,16.427 C13.2@18.116,16.379 18.182,16.313 18.182,11.104 18.821,10.465 18.821,9.249 20.113,7.958 C20.2@20.278,7.958
  Signal Layer 1 w0.152: 42.875,26.746 42.85,26.721 42.85,25.382 48.547,19.685 54.839,19.685 ; 61.824,17.12 v2(63.551,17.12)
  Signal Layer 1 w0.5: 54.839,19.736 58.141,19.736 59.715,18.161 v2(63.5,18.161) 72.009,18.161 73.66,19.812 ; v2(63.551,17.12) 63.856,17.424 71.222,17.424
  Signal Layer 2 w0.152: v2(20.931,21.339) 22.914,21.339 23.072,21.181 23.165,21.181 23.435,20.911 23.435,19.491 v5@23.495,19.431 ; v2(23.369,12.475) 24.817,13.923 v2@25.832,13.923 ; v2@25.832,13.927 25.832,13.94 25.9,14.008 26.2,14.008 v2(26.213,14.021) ; v2(27.356,10.389) 31.479,6.266 v2(31.994,6.266) 32.038,6.266 v2@32.055,6.248
  Bottom Layer w0.152: v2(11.481,22.2) 11.481,18.161 14.61,15.032 14.61,14.661 v5@14.605,14.656 ; v2(11.735,11.76) 14.021,11.76 14.554,12.294 14.554,13.223 14.641,13.31 v5@14.681,13.31 ; v2@20.93,6.325 21.006,6.325 22.022,5.309 v2(25.527,5.309) ; v2(20.98,6.35) 20.32,7.01 20.32,14.518 20.78,14.978 21.15,14.978 v2(21.158,14.986) 22.149,13.995 v2(25.832,13.995) ; v2(27.356,10.389) 27.523,10.222 v2@27.523,6.426 ; v2(27.508,6.401) 27.508,5.791 29.997,3.302 40.361,3.302 ; J3.2@37.182,21.674 38.811,20.044 38.811,12.243 38.235,11.667 J3.10@37.651,11.667 ; 44.152,11.514 44.287,11.649 44.287,11.717 v2(44.315,11.745) 44.827,11.233 51.623,11.233 ; v2(48.387,7.366) 49.733,6.02 v2@49.733,5.012 ; v8(48.425,4.839) 48.425,3.213 v2(48.819,2.819) ; v2(56.617,15.265) 56.606,15.255 56.606,14.488 57.379,13.716 60.396,13.716 v4(60.808,14.128) ; v2(62.662,6.782) 63.128,7.248 v4(63.128,11.028) ; v4@63.957,11.989 v4@64.018,11.928 ; v4@63.983,11.989 64.044,11.989 64.493,12.438 v2(68.214,12.438) ; v4(64.018,13.193) 67.447,13.193 68.313,14.058 68.313,14.122 68.317,14.126 v2@68.373,14.126
  Bottom Layer w1: v2(63.5,18.161) 63.5,19.761
  other v1: 2.023,1.621 2.823,1.621 3.623,1.621 4.423,1.621 5.223,1.621 6.023,1.621 6.823,1.621 7.623,1.621 8.423,1.621 15.623,1.621 16.423,1.621 17.223,1.621 18.023,1.621 18.823,1.621 19.623,1.621 20.423,1.621 21.223,1.621 22.023,1.621 22.823,1.621 23.623,1.621 24.423,1.621 25.223,1.621 26.023,1.621 26.823,1.621 27.623,1.621 28.423,1.621 29.223,1.621 30.023,1.621 30.823,1.621 31.623,1.621 32.423,1.621 33.223,1.621 34.023,1.621 34.823,1.621 35.623,1.621 36.423,1.621 37.223,1.621 38.023,1.621 38.823,1.621 39.623,1.621 40.423,1.621 1.623,2.421 2.423,2.421 3.223,2.421 4.023,2.421 4.823,2.421 5.623,2.421 6.423,2.421 7.223,2.421 17.623,2.421 18.423,2.421 19.223,2.421 20.023,2.421 20.823,2.421 21.623,2.421 22.423,2.421 23.223,2.421 24.023,2.421 24.823,2.421 25.623,2.421 26.423,2.421 27.223,2.421 28.023,2.421 28.823,2.421 29.623,2.421 30.423,2.421 31.223,2.421 32.023,2.421 32.823,2.421 33.623,2.421 34.423,2.421 35.223,2.421 36.023,2.421 36.823,2.421 37.623,2.421 38.423,2.421 39.223,2.421 40.023,2.421 79.223,2.421 80.023,2.421 80.823,2.421 81.623,2.421 82.423,2.421 83.223,2.421 84.023,2.421 84.823,2.421 85.623,2.421 86.423,2.421 2.023,3.221 2.823,3.221 3.623,3.221 4.423,3.221 5.223,3.221 6.023,3.221 6.823,3.221 18.023,3.221 18.823,3.221 19.623,3.221 20.423,3.221 21.223,3.221 22.023,3.221 22.823,3.221 23.623,3.221 24.423,3.221 25.223,3.221 26.023,3.221 29.223,3.221 30.023,3.221 30.823,3.221 42.823,3.221 54.823,3.221 64.423,3.221 65.223,3.221 66.023,3.221 66.823,3.221 67.623,3.221 68.423,3.221 69.223,3.221 70.023,3.221 70.823,3.221 71.623,3.221 72.423,3.221 73.223,3.221 74.023,3.221 74.823,3.221 75.623,3.221 78.823,3.221 79.623,3.221 80.423,3.221 81.223,3.221 82.023,3.221 82.823,3.221 83.623,3.221 84.423,3.221 85.223,3.221 86.023,3.221 86.823,3.221 1.623,4.021 2.423,4.021 3.223,4.021 4.023,4.021 4.823,4.021 5.623,4.021 6.423,4.021 54.423,4.021 64.023,4.021 64.823,4.021 65.623,4.021 66.423,4.021 67.223,4.021 68.023,4.021 68.823,4.021 79.223,4.021 80.023,4.021 80.823,4.021 85.623,4.021 86.423,4.021 2.023,4.821 2.823,4.821 3.623,4.821 4.423,4.821 5.223,4.821 6.023,4.821 6.823,4.821 50.823,4.821 79.623,4.821 80.423,4.821 86.023,4.821 86.823,4.821 1.623,5.621 2.423,5.621 3.223,5.621 4.023,5.621 4.823,5.621 5.623,5.621 6.423,5.621 24.023,5.621 36.023,5.621 36.823,5.621 79.223,5.621 80.023,5.621 86.423,5.621 2.023,6.421 2.823,6.421 3.623,6.421 4.423,6.421 5.223,6.421 6.023,6.421 6.823,6.421 36.423,6.421 50.823,6.421 79.623,6.421 80.423,6.421 86.023,6.421 86.823,6.421 1.623,7.221 2.423,7.221 3.223,7.221 4.023,7.221 4.823,7.221 5.623,7.221 6.423,7.221 7.223,7.221 8.023,7.221 21.623,7.221 40.823,7.221 41.623,7.221 42.423,7.221 43.223,7.221 79.223,7.221 80.023,7.221 80.823,7.221 81.623,7.221 82.423,7.221 83.223,7.221 84.023,7.221 84.823,7.221 85.623,7.221 86.423,7.221 2.023,8.021 2.823,8.021 3.623,8.021 4.423,8.021 5.223,8.021 6.023,8.021 6.823,8.021 7.623,8.021 18.823,8.021 41.223,8.021 42.023,8.021 42.823,8.021 43.623,8.021 44.423,8.021 50.823,8.021 79.623,8.021 80.423,8.021 81.223,8.021 82.023,8.021 82.823,8.021 83.623,8.021 84.423,8.021 85.223,8.021 86.023,8.021 86.823,8.021 4.023,8.821 4.823,8.821 23.223,8.821 35.223,8.821 36.023,8.821 79.223,8.821 80.023,8.821 80.823,8.821 81.623,8.821 82.423,8.821 83.223,8.821 84.023,8.821 84.823,8.821 85.623,8.821 86.423,8.821 79.623,9.621 80.423,9.621 81.223,9.621 82.023,9.621 82.823,9.621 83.623,9.621 84.423,9.621 85.223,9.621 86.023,9.621 86.823,9.621 3.223,10.421 4.023,10.421 23.223,10.421 79.223,10.421 80.023,10.421 80.823,10.421 81.623,10.421 82.423,10.421 83.223,10.421 84.023,10.421 84.823,10.421 85.623,10.421 86.423,10.421 2.023,11.221 2.823,11.221 3.623,11.221 4.423,11.221 41.223,11.221 42.023,11.221 42.823,11.221 1.623,12.021 2.423,12.021 3.223,12.021 4.023,12.021 4.823,12.021 38.423,12.021 40.823,12.021 41.623,12.021 42.423,12.021 2.023,12.821 2.823,12.821 3.623,12.821 4.423,12.821 41.223,12.821 42.023,12.821 42.823,12.821 1.623,13.621 2.423,13.621 3.223,13.621 4.023,13.621 2.023,14.421 2.823,14.421 3.623,14.421 4.423,14.421 70.023,14.421 72.423,14.421 73.223,14.421 74.023,14.421 74.823,14.421 75.623,14.421 76.423,14.421 79.623,14.421 80.423,14.421 81.223,14.421 82.023,14.421 82.823,14.421 83.623,14.421 84.423,14.421 85.223,14.421 86.023,14.421 86.823,14.421 1.623,15.221 2.423,15.221 3.223,15.221 4.023,15.221 40.823,15.221 41.623,15.221 42.423,15.221 43.223,15.221 44.023,15.221 44.823,15.221 68.023,15.221 68.823,15.221 69.623,15.221 79.223,15.221 80.023,15.221 86.423,15.221 2.023,16.021 2.823,16.021 3.623,16.021 4.423,16.021 41.223,16.021 42.023,16.021 42.823,16.021 43.623,16.021 78.823,16.021 79.623,16.021 80.423,16.021 86.023,16.021 86.823,16.021 1.623,16.821 2.423,16.821 3.223,16.821 4.023,16.821 32.023,16.821 32.823,16.821 40.823,16.821 41.623,16.821 42.423,16.821 43.223,16.821 73.623,16.821 74.423,16.821 75.223,16.821 76.023,16.821 76.823,16.821 79.223,16.821 80.023,16.821 86.423,16.821 41.223,17.621 42.023,17.621 74.023,17.621 74.823,17.621 75.623,17.621 76.423,17.621 78.823,17.621 79.623,17.621 80.423,17.621 86.023,17.621 86.823,17.621 4.023,18.421 4.823,18.421 79.223,18.421 80.023,18.421 80.823,18.421 81.623,18.421 82.423,18.421 83.223,18.421 84.023,18.421 84.823,18.421 85.623,18.421 86.423,18.421 2.023,19.221 2.823,19.221 3.623,19.221 4.423,19.221 5.223,19.221 6.023,19.221 6.823,19.221 78.823,19.221 79.623,19.221 80.423,19.221 81.223,19.221 82.023,19.221 82.823,19.221 83.623,19.221 84.423,19.221 85.223,19.221 86.023,19.221 86.823,19.221 1.623,20.021 2.423,20.021 3.223,20.021 4.023,20.021 4.823,20.021 5.623,20.021 6.423,20.021 46.423,20.021 47.223,20.021 48.023,20.021 48.823,20.021 49.623,20.021 50.423,20.021 51.223,20.021 52.023,20.021 52.823,20.021 53.623,20.021 54.423,20.021 55.223,20.021 68.823,20.021 69.623,20.021 70.423,20.021 71.223,20.021 72.023,20.021 72.823,20.021 76.023,20.021 76.823,20.021 79.223,20.021 80.023,20.021 80.823,20.021 82.423,20.021 83.223,20.021 84.023,20.021 84.823,20.021 85.623,20.021 86.423,20.021 87.223,20.021 88.023,20.021 88.823,20.021 89.623,20.021 90.423,20.021 91.223,20.021 92.023,20.021 2.023,20.821 2.823,20.821 3.623,20.821 4.423,20.821 5.223,20.821 6.023,20.821 6.823,20.821 45.223,20.821 46.023,20.821 46.823,20.821 47.623,20.821 48.423,20.821 49.223,20.821 50.023,20.821 50.823,20.821 51.623,20.821 52.423,20.821 53.223,20.821 54.023,20.821 54.823,20.821 55.623,20.821 68.423,20.821 69.223,20.821 70.023,20.821 72.423,20.821 73.223,20.821 74.023,20.821 77.223,20.821 78.823,20.821 79.623,20.821 80.423,20.821 81.223,20.821 82.023,20.821 82.823,20.821 83.623,20.821 84.423,20.821 85.223,20.821 86.023,20.821 86.823,20.821 87.623,20.821 88.423,20.821 89.223,20.821 90.023,20.821 90.823,20.821 91.623,20.821 1.623,21.621 2.423,21.621 3.223,21.621 4.023,21.621 4.823,21.621 5.623,21.621 6.423,21.621 28.823,21.621 29.623,21.621 41.623,21.621 42.423,21.621 44.823,21.621 45.623,21.621 46.423,21.621 47.223,21.621 48.023,21.621 48.823,21.621 49.623,21.621 50.423,21.621 51.223,21.621 52.023,21.621 52.823,21.621 53.623,21.621 54.423,21.621 55.223,21.621 60.023,21.621 60.823,21.621 61.623,21.621 64.023,21.621 68.023,21.621 68.823,21.621 69.623,21.621 70.423,21.621 72.023,21.621 72.823,21.621 73.623,21.621 74.423,21.621 79.223,21.621 80.023,21.621 80.823,21.621 81.623,21.621 82.423,21.621 83.223,21.621 84.023,21.621 84.823,21.621 85.623,21.621 86.423,21.621 87.223,21.621 88.023,21.621 88.823,21.621 89.623,21.621 90.423,21.621 91.223,21.621 92.023,21.621 6.823,22.421 29.223,22.421 30.023,22.421 41.223,22.421 42.023,22.421 45.223,22.421 46.023,22.421 46.823,22.421 47.623,22.421 48.423,22.421 49.223,22.421 50.023,22.421 50.823,22.421 51.623,22.421 52.423,22.421 53.223,22.421 54.023,22.421 54.823,22.421 58.823,22.421 59.623,22.421 60.423,22.421 61.223,22.421 62.023,22.421 64.423,22.421 68.423,22.421 69.223,22.421 70.023,22.421 70.823,22.421 71.623,22.421 72.423,22.421 73.223,22.421 74.023,22.421 74.823,22.421 75.623,22.421 79.623,22.421 80.423,22.421 81.223,22.421 82.023,22.421 82.823,22.421 83.623,22.421 84.423,22.421 85.223,22.421 86.023,22.421 86.823,22.421 87.623,22.421 88.423,22.421 89.223,22.421 90.023,22.421 90.823,22.421 91.623,22.421 40.023,23.221 40.823,23.221 41.623,23.221 42.423,23.221 80.023,23.221 80.823,23.221 81.623,23.221 82.423,23.221 83.223,23.221 84.023,23.221 88.823,23.221 89.623,23.221 90.423,23.221 91.223,23.221 92.023,23.221 39.623,24.021 40.423,24.021 41.223,24.021 42.023,24.021 80.423,24.021 81.223,24.021 82.023,24.021 82.823,24.021 83.623,24.021 89.223,24.021 90.023,24.021 90.823,24.021 91.623,24.021 16.823,24.821 17.623,24.821 20.023,24.821 28.823,24.821 29.623,24.821 30.423,24.821 34.423,24.821 39.223,24.821 40.023,24.821 40.823,24.821 41.623,24.821 42.423,24.821 81.623,24.821 82.423,24.821 83.223,24.821 89.623,24.821 90.423,24.821 91.223,24.821 92.023,24.821 29.223,25.621 30.023,25.621 33.223,25.621 34.023,25.621 39.623,25.621 40.423,25.621 41.223,25.621 42.023,25.621 82.023,25.621 82.823,25.621 83.623,25.621 90.023,25.621 90.823,25.621 91.623,25.621 28.823,26.421 32.823,26.421 33.623,26.421 40.023,26.421 40.823,26.421 41.623,26.421 42.423,26.421 82.423,26.421 83.223,26.421 89.623,26.421 90.423,26.421 91.223,26.421 92.023,26.421 14.823,27.221 31.623,27.221 32.423,27.221 33.223,27.221 39.623,27.221 40.423,27.221 41.223,27.221 42.023,27.221 82.023,27.221 82.823,27.221 83.623,27.221 89.223,27.221 90.023,27.221 90.823,27.221 91.623,27.221 8.023,28.021 8.823,28.021 9.623,28.021 10.423,28.021 11.223,28.021 12.023,28.021 12.823,28.021 13.623,28.021 14.423,28.021 15.223,28.021 24.823,28.021 31.223,28.021 32.023,28.021 32.823,28.021 33.623,28.021 40.023,28.021 40.823,28.021 41.623,28.021 42.423,28.021 82.423,28.021 83.223,28.021 84.023,28.021 84.823,28.021 88.023,28.021 88.823,28.021 89.623,28.021 90.423,28.021 91.223,28.021 92.023,28.021 7.623,28.821 8.423,28.821 9.223,28.821 10.023,28.821 10.823,28.821 11.623,28.821 12.423,28.821 13.223,28.821 14.023,28.821 14.823,28.821 19.623,28.821 20.423,28.821 21.223,28.821 22.023,28.821 22.823,28.821 23.623,28.821 24.423,28.821 25.223,28.821 30.023,28.821 30.823,28.821 31.623,28.821 32.423,28.821 33.223,28.821 34.023,28.821 38.823,28.821 39.623,28.821 40.423,28.821 41.223,28.821 42.023,28.821 42.823,28.821 82.823,28.821 83.623,28.821 84.423,28.821 85.223,28.821 86.023,28.821 86.823,28.821 87.623,28.821 88.423,28.821 89.223,28.821 90.023,28.821 8.023,29.621 8.823,29.621 9.623,29.621 10.423,29.621 11.223,29.621 12.823,29.621 13.623,29.621 14.423,29.621 18.423,29.621 19.223,29.621 20.023,29.621 20.823,29.621 21.623,29.621 22.423,29.621 23.223,29.621 24.023,29.621 24.823,29.621 25.623,29.621 29.623,29.621 30.423,29.621 31.223,29.621 32.023,29.621 32.823,29.621 33.623,29.621 34.423,29.621 35.223,29.621 36.023,29.621 37.623,29.621 38.423,29.621 39.223,29.621 40.023,29.621 40.823,29.621 41.623,29.621 42.423,29.621 82.423,29.621 83.223,29.621 84.023,29.621 84.823,29.621 85.623,29.621 86.423,29.621 87.223,29.621 88.023,29.621 88.823,29.621 89.623,29.621 7.623,30.421 8.423,30.421 9.223,30.421 10.023,30.421 10.823,30.421 11.623,30.421 12.423,30.421 13.223,30.421 14.023,30.421 18.823,30.421 19.623,30.421 20.423,30.421 21.223,30.421 22.023,30.421 22.823,30.421 23.623,30.421 24.423,30.421 25.223,30.421 28.423,30.421 29.223,30.421 30.023,30.421 34.023,30.421 34.823,30.421 35.623,30.421 36.423,30.421 37.223,30.421 40.423,30.421 41.223,30.421 42.023,30.421 42.823,30.421 82.823,30.421 83.623,30.421 86.823,30.421 87.623,30.421 88.423,30.421 89.223,30.421 90.023,30.421 8.023,31.221 8.823,31.221 9.623,31.221 10.423,31.221 11.223,31.221 12.023,31.221 12.823,31.221 13.623,31.221 14.423,31.221 18.423,31.221 19.223,31.221 20.023,31.221 20.823,31.221 21.623,31.221 22.423,31.221 23.223,31.221 24.023,31.221 28.023,31.221 28.823,31.221 29.623,31.221 30.423,31.221 34.423,31.221 35.223,31.221 36.023,31.221 36.823,31.221 79.223,31.221 80.023,31.221 80.823,31.221 81.623,31.221 82.423,31.221 83.223,31.221 87.223,31.221 88.023,31.221 88.823,31.221 89.623,31.221 34.023,32.021 79.623,32.021 86.823,32.021 87.623,32.021 88.423,32.021 89.223,32.021 90.023,32.021 34.423,32.821
  other v2: 10.414,4.597 14.402,4.801 17.094,4.928 49.759,5.08 37.861,7.383 73.523,9.136 68.341,14.19 15.342,16.688 81.737,20.168 71.298,21.057 44.008,28.211 12.156,29.608
  other v4: 60.808,11.028 61.968,11.028 59.918,11.963 60.808,11.963 61.968,11.963 63.128,11.963 64.018,11.963 59.918,13.193 60.808,13.193 61.968,13.193 63.128,13.193 61.968,14.128 63.128,14.128
  other v5: 45.425,4.839 46.425,4.839 14.61,13.384 14.01,13.984 14.61,13.984 15.21,13.984 14.61,14.584 23.435,17.082 22.285,18.232 23.435,18.232 24.585,18.232 23.435,19.382
  other v6: 82.55,4.293 32.182,31.42 33.223,31.572 32.182,32.512 32.08,33.604 33.223,33.63 34.214,33.909
  other v8: 47.425,4.839
GPIO0: R110.1 U1.5 | length 9.8
  Top Layer w0.152: U1.5@23.635,16.307 23.654,16.288 23.654,15.741 v2(23.673,15.723)
  Signal Layer 2 w0.152: v2(26.518,14.884) 27.178,14.884 28.272,13.791 29.084,13.791 v2@31.064,11.811
  Bottom Layer w0.152: v2(23.673,15.723) 23.701,15.694 23.701,15.499 24.366,14.834 26.362,14.834 26.385,14.856 26.489,14.856 v2(26.518,14.884)
  other v2: 31.079,11.803
GPIO1: R66.1 U1.6 | length 8.6
  Top Layer w0.152: U1.6@24.035,16.307 24.059,16.283 24.059,15.939 24.099,15.899 24.099,15.744 24.204,15.639 v2(24.204,15.599)
  Signal Layer 2 w0.152: v2(26.518,15.474) 26.537,15.494 27.076,15.494 28.211,14.36 29.665,14.36 v2@30.785,13.24
  Bottom Layer w0.152: v2(24.204,15.599) 24.608,15.195 26.225,15.195 26.505,15.474 v2(26.518,15.474)
  other v2: 30.8,13.225
GPIO4: R17.1 R99.1 U1.22 | length 24.9
  Top Layer w0.152: v2(10.236,11.328) 10.77,10.795 15.61,10.795 15.763,10.643 v2(15.773,10.643) ; v2(17.374,7.544) 17.45,7.62 R99.1@17.602,7.62 ; U1.22@22.835,20.157 22.859,20.18 22.859,20.586 22.988,20.715 v2(22.988,20.755)
  Bottom Layer w0.152: v2(17.374,7.544) 16.459,7.544 15.519,8.484 15.519,10.389 v2(15.773,10.643) 16.789,10.643 18.694,12.548 18.694,16.231 22.976,20.512 22.976,20.743 v2(22.988,20.755)
GPIO5: R19.1 R100.2 U1.23 | length 21.6
  Top Layer w0.152: v2(10.211,10.592) 10.211,10.534 10.228,10.517 10.382,10.363 v2(14.961,10.363) ; v2(22.428,20.702) 22.432,20.698 22.432,20.16 U1.23@22.435,20.157
  Bottom Layer w0.152: v2(9.347,9.119) 9.652,9.119 10.211,9.677 v2(10.211,10.592) ; v2(14.961,10.363) 14.961,10.871 16.535,12.446 17.805,12.446 18.237,12.878 ; 18.263,12.878 18.263,16.332 22.4,20.47 22.4,20.673 v2(22.428,20.702)
GPIO6: R98.1 U1.31 | length 12.3
  Top Layer w0.152: R98.1@14.695,9.029 14.695,9.129 14.968,9.402 16.056,9.402 16.763,10.108 v2(16.993,10.109) v2(16.993,10.109) ; v2(20.879,16.967) 20.909,16.967 21.15,17.208 21.311,17.208 U1.31@21.336,17.232
  Bottom Layer w0.152: v2(16.993,10.109) 17.501,10.109 19.456,12.065 19.456,15.773 20.649,16.966 v2(20.879,16.967) v2(20.879,16.967)
GPIO7: R107.1 U1.30 | length 10.9
  Top Layer w0.152: R107.1@17.332,8.825 17.501,8.994 v2(17.501,9.347) 17.512,9.358 17.512,10.762 v2(17.523,10.773) ; v2(20.93,17.602) 20.944,17.617 21.351,17.617 U1.30@21.361,17.628
  Bottom Layer w0.152: v2(17.523,10.773) 19.101,12.351 19.101,16.078 20.625,17.602 v2(20.93,17.602)
GPIO11: U1.13
GPIO_NF: Q3.5 Q9.5 R107.2 R108.2 | length 15.7
  Top Layer w0.15: Q9.5@10.653,5.563 10.704,5.512 v2@11.049,5.512
  Top Layer w0.152: Q3.5@14.478,5.563 14.513,5.527 15.453,5.527 v2(16.053,4.928) 16.053,4.343 R108.2@16.027,4.318
  Signal Layer 2 w0.152: v2(11.125,5.537) 11.125,4.369 11.557,3.937 15.102,3.937 16.025,4.859 v2@16.025,4.93
  Bottom Layer w0.152: v2@16.027,4.877 16.027,4.902 v2(16.053,4.928) 18.085,6.96 18.085,7.696 17.475,8.306 16.815,8.306 v2(16.154,8.966)
GPIO_PF: Q3.2 Q9.2 R97.1 R98.2 | length 11.6
  Top Layer w0.15: v2(8.255,5.512) 8.28,5.537 8.585,5.537 Q9.2@8.611,5.512 ; v2(12.014,5.486) 12.035,5.507 12.451,5.507 Q3.2@12.471,5.486
  Top Layer w0.152: R97.1@12.459,8.638 12.459,8.588 13.118,7.929 14.595,7.929 14.653,7.871 R98.2@14.695,7.829 14.58,7.714 v2(14.58,7.62)
  Signal Layer 1 w0.15: v2(8.255,5.512) 9.068,6.325 11.176,6.325 v2(12.014,5.486) 12.446,5.486 v2(14.58,7.62)
HIDRV1: R37.2 U7.27 | length 25.2
  Top Layer w0.152: v2(59.766,15.951) v2@59.774,15.951
  Top Layer w0.254: v2(59.766,15.951) 60.223,15.494 U7.27@60.223,15.138
  Signal Layer 2 w0.5: v2(50.739,36.466) 50.739,29.068 59.715,20.091 v2@59.715,15.977
HIDRV2: R34.2 U7.19 | length 21
  Top Layer w0.152: U7.19@64.218,15.136 U7.19@64.267,15.185
  Top Layer w0.254: U7.19@64.22,14.978 64.889,14.978 v2(65.634,15.723)
  Top Layer w0.5: v2(74.422,31.064) 74.481,31.123 R34.2@74.615,31.123
  Signal Layer 2 w0.5: v2(65.634,15.723) 65.634,22.276 v2(74.422,31.064)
